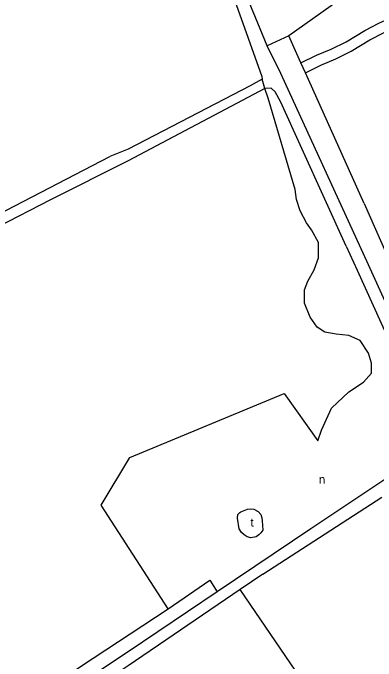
# Model space of a CAD drawing. Extents: x 158358 to 160383, y 379531 to 380764.
# Drawn here: x 159045.9 to 159216.2, y 379916.8 to 380220.5 of the extents above; entities that cross this region are included whole.
import ezdxf

# ---------------------------------------------------------------- set-up
doc = ezdxf.new("R2010")
doc.units = 0
for name, color, linetype in [('BLT_Basislijn', 7, 'Continuous'), ('BLT_Centroide', 7, 'Continuous'), ('BLT_Vlakafsluiter', 7, 'Continuous')]:
    doc.layers.add(name, color=color, linetype=linetype)

msp = doc.modelspace()

# ---------------------------------------------------------------- linework, layer by layer
at = {"layer": 'BLT_Basislijn'}
for p, q in [((159175.31, 380209.78), (159165.17, 380205.1)), ((159008.48, 380110.26), (159091.4, 380153.19)), ((159063.5, 380132.95), (159032.57, 380117)), ((159210.62, 380131.18), (159259.52, 380020.21)), ((159163.13, 379957.51), (159152.55, 379950.32))]:
    msp.add_line(p, q, dxfattribs=at)
for points in [[(159205.89, 380300.06), (159233.79, 380251.29), (159175.31, 380209.78)], [(159181.03, 380197.05), (159188.24, 380200.64), (159195.23, 380203.52), (159202.18, 380207.01), (159210.97, 380212.28), (159217.58, 380215.63), (159233.46, 380222.94), (159246.59, 380229.57), (159263.22, 380238.61), (159271.15, 380242.3), (159279.19, 380247.09), (159282.74, 380250.27), (159286.8, 380253.31), (159291.21, 380255.55), (159297.33, 380257.54), (159310.66, 380260.6)], [(159135.84, 380258.41), (159149.92, 380226.84), (159162.71, 380190.63), (159162.86, 380189.52)], [(159165.17, 380205.1), (159152.3, 380236.38), (159146.49, 380248.85)], [(159183.08, 380192.48), (159190.31, 380196.08), (159197.3, 380198.97), (159204.59, 380202.62), (159213.39, 380207.9), (159219.76, 380211.13), (159223.39, 380212.8)], [(159181.03, 380197.05), (159175.31, 380209.78)], [(159246.18, 380011.53), (159249.72, 380020.35), (159242.08, 380037.85), (159212.76, 380102.49), (159171.52, 380192.1), (159165.17, 380205.1)], [(159183.08, 380192.48), (159181.03, 380197.05)], [(159210.62, 380131.18), (159183.08, 380192.48)], [(159162.86, 380189.52), (159157.2, 380186.31), (159100, 380156.65), (159091.4, 380153.19)], [(159164.02, 380185.04), (159100, 380151.25), (159063.5, 380132.95)], [(159118.75, 379941.35), (159087.29, 379989.82), (159100.68, 380012.16), (159173.07, 380042.24), (159188.85, 380020.03), (159190.57, 380024.98), (159195.3, 380035.24), (159203.54, 380042.97), (159210.41, 380047.47), (159214.05, 380051.77), (159214.05, 380056.4), (159212.73, 380061.03), (159208.76, 380066.98), (159203.46, 380069.3), (159197.51, 380069.96), (159192.22, 380070.95), (159188.58, 380073.27), (159185.27, 380077.9), (159182.63, 380084.51), (159182.63, 380090.8), (159184.28, 380094.76), (159187.26, 380100.05), (159189.24, 380105.68), (159189.24, 380112.95), (159185.94, 380118.91), (159183.62, 380122.21), (159180.64, 380127.84), (159178.99, 380133.13), (159178.33, 380137.76), (159165.69, 380180.53), (159164.02, 380185.04)], [(159202.17, 380111.15), (159171.35, 380178.94), (159168.91, 380183.48), (159167, 380185.23), (159164.02, 380185.04)], [(159202.17, 380111.15), (159207.31, 380100), (159236.59, 380035.42), (159243.21, 380020.25), (159241.51, 380016), (159185.59, 379978.81), (159141.72, 379949.29)], [(159163.13, 379957.51), (159218.93, 379993.53)], [(159118.75, 379941.35), (159138.33, 379954.66), (159141.72, 379949.29)], [(159152.55, 379950.32), (159100, 379914.6), (159090.06, 379908.02)], [(159091.84, 379699.34), (159234.83, 379829.68), (159152.55, 379950.32)], [(159141.72, 379949.29), (159100, 379921.21), (159087, 379912.56)], [(158743.24, 379690.45), (158750.11, 379695.14), (158799.36, 379728.24), (158955.39, 379832.56), (159077.54, 379914.23), (159118.75, 379941.35)]]:
    msp.add_lwpolyline(points, dxfattribs=at)
msp.add_lwpolyline([(159151.38, 379985.46), (159152.37, 379986.41), (159152.88, 379986.74), (159155.13, 379987.7), (159155.89, 379987.99), (159157.39, 379988.21), (159158.93, 379987.96), (159160.88, 379986.89), (159162.2, 379985.5), (159162.67, 379983.92), (159162.89, 379982.45), (159163.15, 379978.19), (159162.23, 379976.84), (159161.21, 379975.96), (159160.07, 379975.08), (159157.54, 379974.6), (159155.71, 379975.08), (159154.31, 379975.97), (159153.06, 379977.05), (159152, 379978.71), (159151.31, 379983.81)], close=True, dxfattribs=at)
at = {"layer": 'BLT_Vlakafsluiter'}
msp.add_line((159164.02, 380185.04), (159162.86, 380189.52), dxfattribs=at)

# ---------------------------------------------------------------- texts
at = {"layer": 'BLT_Centroide'}
for s, p in [('n', (159189.43, 379999.92)), ('t', (159157.32, 379979.81))]:
    msp.add_text(s, height=4, dxfattribs=at).set_placement(p)

doc.saveas('drawing.dxf')
